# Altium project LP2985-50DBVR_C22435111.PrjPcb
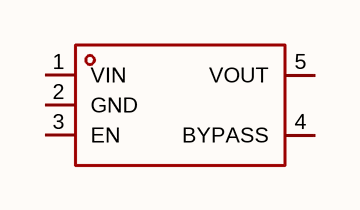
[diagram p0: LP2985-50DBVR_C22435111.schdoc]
1 sheet, 1 parts. Net scope: global (net labels, ports and power ports of the same name join across sheets).

## Sheet LP2985-50DBVR_C22435111.schdoc
size 127 x 101 mm

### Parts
U?  lp2985-50dbvr_c22435111  [SOT-23-5_L3.0-W1.6-P0.95-LS2.8-BR]  (value not drawn)

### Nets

Not connected (* = marked no-connect by the designer): U? 1(VIN) 2(GND) 3(EN) 4(BYPASS) 5(VOUT)

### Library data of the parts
U? = lp2985-50dbvr_c22435111: 输出极性:正极;工作电压:18V;输出电压:5V;输出电流:150mA;电源纹波抑制比(PSRR):70dB@(1kHz);输出类型:固定;; Manufacturer: TECH PUBLIC(台舟); AddInBom: yes; ModelId: 72410e292833493f86746b22636ce101; ModelTransform: 110.236,116.1415,0,0,0,0,0.002,0.001,0; Output Configuration: 正极; Voltage - Supply: 18V; Output Voltage: 5V; Output Current: 150mA; Voltage Dropout: 85mV@(100mA); standby current: 10uA; Output Type: 固定; Number of Outputs: 1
